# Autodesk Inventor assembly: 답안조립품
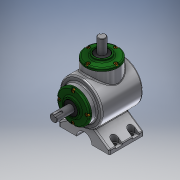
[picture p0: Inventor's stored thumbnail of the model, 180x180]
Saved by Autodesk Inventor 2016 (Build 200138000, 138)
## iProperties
Created: 2017-04
Part Number: 답안조립품
Material: 일반
Document SubType Name: Assembly
Designer: SMW
Author: SMW
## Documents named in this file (14)
- C:\Users\CAMTIC\Desktop\470407V1026\답안조립품.iam
- C:\Users\CAMTIC\Desktop\470407V1026\1-본체.ipt
- C:\Users\CAMTIC\Desktop\470407V1026\메인 베벨기어.ipt
- C:\Users\CAMTIC\Desktop\470407V1026\메인 축.ipt
- 메인 축.ipt
- C:\Users\CAMTIC\Desktop\470407V1026\베어링 6203.ipt
- C:\Users\CAMTIC\Desktop\470407V1026\볼트 M4.ipt
- C:\Users\CAMTIC\Desktop\470407V1026\서브 베벨기어.ipt
- C:\Users\CAMTIC\Desktop\470407V1026\서브 축.ipt
- 서브 축.ipt
- C:\Users\CAMTIC\Desktop\470407V1026\오일실 17 32 8.ipt
- C:\Users\CAMTIC\Desktop\470407V1026\커버.ipt
- C:\Users\CAMTIC\Desktop\470407V1026\키 4x4.ipt
- C:\Users\CAMTIC\Desktop\470407V1026\키 5x5.ipt
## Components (1 placed, 1 different names)
1. 1-본체:1
